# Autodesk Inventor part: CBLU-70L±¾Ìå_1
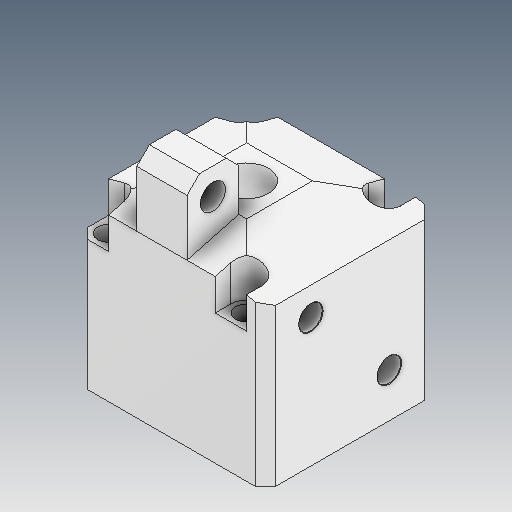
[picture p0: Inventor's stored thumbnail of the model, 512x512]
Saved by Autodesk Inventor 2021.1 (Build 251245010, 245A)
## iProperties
Created: 2021-05
Part Number: CBLU-70L±¾Ìå_1
Material: Ogólny
Document SubType Name: Modeling
Designer: user
Density: 1 g/cm^3
Appearance: Domyślna
Author: user
Revision Number: ÈÎºÎ
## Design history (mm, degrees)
feature "ÊäÈë1"
feature "ÊäÈë2"
node "Bryła1"
node "Bryła2"
